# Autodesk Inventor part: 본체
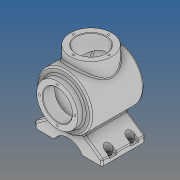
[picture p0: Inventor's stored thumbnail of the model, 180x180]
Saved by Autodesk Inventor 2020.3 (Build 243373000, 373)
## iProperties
Created: 2021-04
Part Number: 본체
Material: 알루미늄 6061
Document SubType Name: Modeling
Designer: EZDESIGN
Density: 2.7 g/cm^3
Appearance: 기본값
Author: EZDESIGN
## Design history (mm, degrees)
sketch "스케치1"
  geometry: L1 (0, 60)-(0, -60); L2 (27, 60)-(38, 60); L3 (38, 60)-(38, 48); L4 (38, 48)-(50, 48); L5 (50, 48)-(50, -37.05); L6 (50, -60)-(27, -60); L7 (27, 60)-(27, 38); L8 (27, 38)-(37, 38); L9 (40, 35)-(40, -39.903); L10 (40, -52.683)-(40, -52.948); L11 (40, -41.916)-(40, -52.683); L12 (50, -48.336)-(50, -60); L13 (50, -37.05)-(50, -48.336); A1 r 113 centre (0, 53) between (-82.658, -24.049) and (0, -60); A2 r 103 centre (0, 53) between (-75.343, -17.231) and (0, -50); A3 r 103 centre (0, 53) between (40, -41.916) and (50, -37.05); A4 r 103 centre (0, 53) between (0, -50) and (38.11, -42.69); A5 r 113 centre (0, 53) between (0, -60) and (50, -48.336); A6 r 3 centre (37, -39.903) between (38.11, -42.69) and (40, -39.903); A7 r 3 centre (37, 35) between (40, 35) and (37, 38); 2 further points
  constraints: 26 end point, 17 point on circle, 12 perpendicular, 7 centre point, 6 tangent, 3 point on line, 2 horizontal alignment, 2 vertical, 1 coincident, 1 equal radius, 1 horizontal, 1 midpoint
  dimensions: "d0" = 12 distance between parallel lines of L4 L2; "d1" = 108 distance of L4.end L6.start; "d2" = 100 diameter of L5 L1; "d3" = 76 diameter of L3 L1; "d4" = 54 diameter of L7 L1; "d5" = 80 diameter of L9 L1; "d6" = 22 distance of L2.start L7.end; "d7" = 113 radius of A1; "d8" = 10 radial gap between concentric circles of A1 A2; "d9" = 3 radius of A6
revolve "회전1" sketch "스케치1" stored, may be unused: angle "d10" = 90 deg
chamfer "모따기1" distance "d11" = 1; stored, may be unused: second distance "d12" = 2, angle "d13" = 45 deg
node "작업 평면1"
sketch "스케치4"
  geometry: A1 r 32.5 centre (0, 0) between (0, 32.5) and (0, -32.5); 3 further points
  constraints: 4 point on circle, 2 horizontal alignment, 2 vertical alignment, 1 centre point, 1 coincident
  dimensions: "d24" = 65 diameter of A1
hole "구멍1" sketch "스케치4" at (0, 32.5), (0, -32.5), (32.5, 0), (-32.5, 0) diameter "d25" = 3.45873; stored, may be unused: countersink angle "d29" = 90 deg, drill point angle "d31" = 118 deg; dims "d26" = 8, "d27" = 4, "d28" = 2, "d30" = 10
sketch "스케치7"
  geometry: L1 (-9.425, -30.186)-(-17.608, -35.916); L2 (-62, -67)-(-62, -77); L3 (-62, -77)-(62, -77); L4 (62, -77)-(62, -67); L5 (62, -67)-(17.608, -35.916); L6 (-9.425, -30.186)-(9.425, -30.186); L7 (0, 0)-(0, -81.277); L8 (17.608, -35.916)-(9.425, -30.186); L9 (-17.608, -35.916)-(-62, -67); L10 (-62, -62)-(88.458, -62); C1 r 50 at (0, 0) reference; A1 r 30 centre (0, -92) between (27.485, -104.024) and (-29.766, -88.263); A2 r 40 centre (0, 0) between (17.608, -35.916) and (-17.608, -35.916) reference; 6 further points
  constraints: 20 end point, 4 point on circle, 2 horizontal, 2 midpoint, 2 perpendicular, 2 vertical, 2 vertical alignment, 1 centre point, 1 collinear, 1 point on line, 1 tangent
  dimensions: "d44" = 30 radius of A1; "d45" = 10 distance of L2.start L2.end; "d46" = 10 distance of L3.end L4.end; "d47" = 77 distance from line of L3 L7.start; "d48" = 55 deg angle of L2 L1; "d49" = 55 deg angle of L4 L5; "d50" = 124 distance of L2.end L3.end; "d51" = 15 distance between parallel lines of L3 L10
extrude "돌출3" join sketch "스케치7" stored distance "d52" = 80; taper "d53" = 0 deg
node "작업 평면3"
sketch "스케치10"
  geometry: L1 (36.019, -80)-(36.019, 0) reference; L2 (-87.981, -80)-(-87.981, 0) reference; L3 (0.713, -80)-(36.019, -80) reference; 5 further points
  constraints: 2 horizontal alignment, 2 vertical alignment
  dimensions: "d56" = 8 distance from line of point (28.019, -60) L1; "d57" = 8 distance from line of L2 point (-79.981, -60); "d58" = 108 distance of point (28.019, -60) point (-79.981, -60) (derived); "d59" = 20 distance from line of point (28.019, -60) L3; "d60" = 40 distance of point (28.019, -20) point (28.019, -60)
hole "구멍3" sketch "스케치10" diameter "d61" = 9; stored, may be unused: countersink angle "d65" = 90 deg, drill point angle "d67" = 118 deg; dims "d62" = 8, "d63" = 14, "d64" = 20, "d66" = 26
node "작업 평면4"
sketch "스케치13"
  geometry: L1 (-63.981, 20)-(12.019, 20) reference; C1 r 38 at (-25.981, -42); 1 further point
  constraints: 1 centre point, 1 vertical alignment
  dimensions: "d70" = 76 diameter of C1; "d71" = 62 distance from line of L1 C1.centre
extrude "돌출4" join sketch "스케치13" stored distance "d72" = 10; taper "d73" = 0 deg; dims "d0" = 12, "d1" = 108, "d2" = 100, "d3" = 76, "d4" = 54, "d5" = 80, "d6" = 22, "d7" = 113, "d8" = 10, "d9" = 3
sketch "스케치14"
  geometry: L1 (38, -62)-(-38, -62) reference; C1 r 38 at (0, 0) reference; C2 r 27 at (0, 0); 1 further point
  constraints: 1 centre point, 1 coincident
  dimensions: "d75" = 54 diameter of C2
extrude "돌출5" cut sketch "스케치14" stored distance "d76" = 10; taper "d77" = 0 deg; dims "d0" = 12, "d1" = 108, "d2" = 100, "d3" = 76, "d4" = 54, "d5" = 80, "d6" = 22, "d7" = 113, "d8" = 10, "d9" = 3
sketch "스케치15"
  geometry: C1 r 27 at (0, 0) reference; C2 r 38 at (0, 0) reference; A1 r 32.5 centre (0, 0) between (-32.5, 0) and (0, -32.5); 3 further points
  constraints: 4 point on circle, 2 horizontal alignment, 2 vertical alignment, 1 centre point, 1 concentric
  dimensions: "d78" = 65 diameter of A1
hole "구멍4" sketch "스케치15" at (-32.5, 0), (0, -32.5), (0, 32.5), (32.5, 0) diameter "d79" = 3.45873; stored, may be unused: countersink angle "d83" = 90 deg, drill point angle "d85" = 118 deg; dims "d80" = 8, "d81" = 14, "d82" = 20, "d84" = 10
chamfer "모따기3" distance "d86" = 1; stored, may be unused: second distance "d87" = 2, angle "d88" = 45 deg
fillet "모깎기1" dims "d89" = 3
sketch "스케치16"
  geometry: L1 (8, 17)-(8, -57) reference; L2 (5, -60)-(-32.576, -60) reference; L3 (-32.576, -60)-(-32.576, 20) reference; L4 (-32.576, 20)-(5, 20) reference; L5 (-113, 20)-(-75.424, 20) reference; L6 (-75.424, 20)-(-75.424, -60) reference; L7 (-75.424, -60)-(-113, -60) reference; L8 (-116, -57)-(-116, 17) reference; L9 (0, 7)-(8, 7); L10 (0, -7)-(8, -7); L11 (0, -33)-(8, -33); L12 (0, -47)-(8, -47); L13 (-108, -47)-(-116, -47); L14 (-108, -33)-(-116, -33); L15 (-108, -7)-(-116, -7); L16 (-108, 7)-(-116, 7); C1 r 4.5 at (0, -40) reference; C2 r 4.5 at (-108, 0) reference; C3 r 4.5 at (-108, -40) reference; C4 r 4.5 at (0, 0) reference; A1 r 3 centre (5, 17) between (8, 17) and (5, 20) reference; A2 r 3 centre (5, -57) between (5, -60) and (8, -57) reference; A3 r 3 centre (-113, -57) between (-116, -57) and (-113, -60) reference; A4 r 3 centre (-113, 17) between (-113, 20) and (-116, 17) reference; A5 r 7 centre (0, -40) between (0, -33) and (0, -47) reference; A6 r 7 centre (-108, 0) between (-108, -7) and (-108, 7) reference; A7 r 7 centre (-108, -40) between (-108, -47) and (-108, -33) reference; A8 r 7 centre (0, 0) between (0, 7) and (0, -7) reference; 1 further point
  constraints: 16 end point, 16 point on line, 8 point on circle, 4 tangent, 3 perpendicular, 1 parallel
extrude "돌출6" cut sketch "스케치16" distance "d90" = 14; taper "d91" = 0 deg
fillet "모깎기2" dims "d92" = 3
fillet "모깎기3" dims "d93" = 3
node "작업 평면10"
sketch "스케치22"
  geometry: L1 (-41.242, 43.086)-(41.242, 43.086); L2 (41.242, 43.086)-(41.242, -43.086); L3 (41.242, -43.086)-(-41.242, -43.086); L4 (-41.242, -43.086)-(-41.242, 43.086); L5 (-41.242, 0)-(41.242, 0); L6 (0, 43.086)-(0, -43.086); 2 further points
  constraints: 5 midpoint, 4 end point, 1 coincident, 2 other
  dimensions: "d97" = 86.17112 distance of L6.start L6.end; "d98" = 82.48327 distance of L5.start L5.end
extrude "돌출7" join sketch "스케치22" stored distance "d100" = 10; taper "d101" = 0 deg
node "솔리드1"
node "절단 모서리 투영1"
node "절단 모서리 투영3"
node "절단 모서리 투영4"
node "절단 모서리 투영5"
feature "A9D066F2-1C7D-4E18-AEED-F7BC21143FA4" dims "d61" = 9, "d62" = 8, "d63" = 14, "d64" = 20, "d65" = 90 deg, "d66" = 26, "d67" = 118 deg
other parameters: "d14" = 65, "d55" = -26, "d69" = -142
